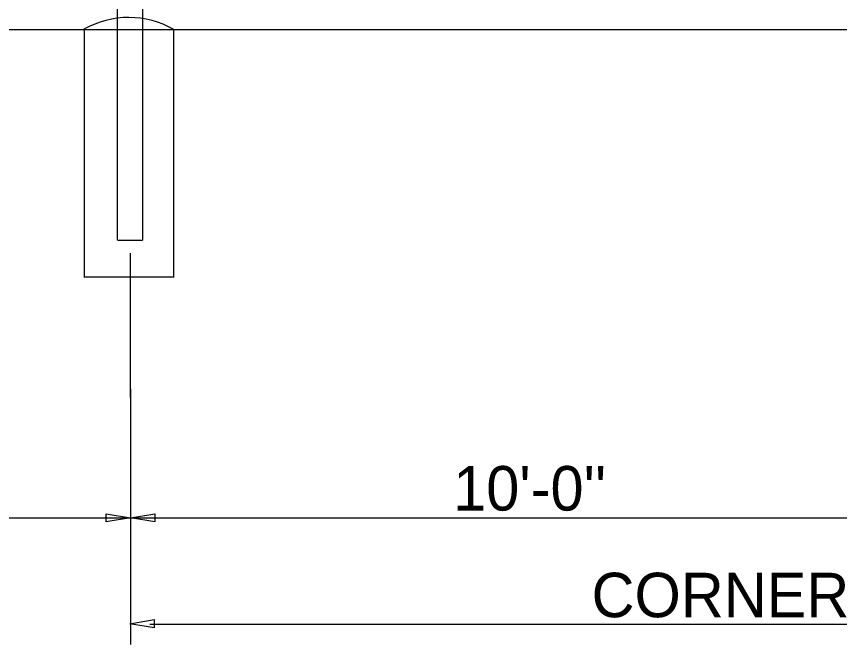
# Model space of a CAD drawing. Extents: x 0 to 2.85, y -0.1 to 1.83.
# Drawn here: x 2.0475 to 2.2325, y 0.6673 to 0.8085 of the extents above; entities that cross this region are included whole.
import ezdxf

# ---------------------------------------------------------------- set-up
doc = ezdxf.new("R2010")
doc.units = 0
for name, color, linetype in [('CT_CSHT_GeneralLabel', 7, 'Continuous'), ('CT_Dimensions', 7, 'Continuous'), ('sb_Chainlink Fence', 7, 'Continuous'), ('sb_Existing Concrete', 7, 'Continuous'), ('sb_Existing Structural Steel', 7, 'Continuous')]:
    doc.layers.add(name, color=color, linetype=linetype)

msp = doc.modelspace()

# ---------------------------------------------------------------- linework, layer by layer
at = {"layer": 'CT_Dimensions'}
for p, q in [((2.07311, 0.74717), (2.07311, 0.75527)), ((2.07311, 0.72287), (2.07311, 0.74724)), ((2.07311, 0.72483), (2.07311, 0.66733)), ((1.87875, 0.6958), (2.07311, 0.6958)), ((2.07311, 0.6958), (2.26747, 0.6958)), ((2.07745, 0.6719), (2.45747, 0.6719))]:
    msp.add_line(p, q, dxfattribs=at)
for points in [[(2.06764, 0.69672), (2.07314, 0.6958), (2.06764, 0.69489)], [(2.07858, 0.69488), (2.07309, 0.6958), (2.07858, 0.69671)], [(2.07843, 0.67108), (2.07293, 0.672), (2.07843, 0.67292)]]:
    msp.add_lwpolyline(points, close=True, dxfattribs=at)
at = {"layer": 'sb_Chainlink Fence'}
msp.add_line((1.88005, 0.80558), (2.44689, 0.80553), dxfattribs=at)
at = {"layer": 'sb_Existing Concrete'}
for p, q in [((2.06279, 0.74985), (2.06279, 0.80546)), ((2.08288, 0.74985), (2.08288, 0.80546)), ((2.06279, 0.74994), (2.08288, 0.74994))]:
    msp.add_line(p, q, dxfattribs=at)
msp.add_arc((2.0727, 0.78798), 0.02029, 59.953, 119.6876, dxfattribs=at)
at = {"layer": 'sb_Existing Structural Steel'}
for p, q in [((2.07021, 0.8072), (2.07031, 0.91755)), ((2.07586, 0.80745), (2.07595, 0.91784)), ((2.07021, 0.75818), (2.07021, 0.8072)), ((2.07586, 0.75822), (2.07586, 0.80745)), ((2.07584, 0.75817), (2.07025, 0.75817))]:
    msp.add_line(p, q, dxfattribs=at)

# ---------------------------------------------------------------- texts
at = {"layer": 'CT_CSHT_GeneralLabel'}
msp.add_text('CORNER POST ASSEMBLY', height=0.01, dxfattribs=at).set_placement((2.17678, 0.67346))
at = {"layer": 'CT_Dimensions'}
msp.add_text("10'-0''", height=0.01, dxfattribs=at).set_placement((2.14566, 0.69744))

doc.saveas('drawing.dxf')
